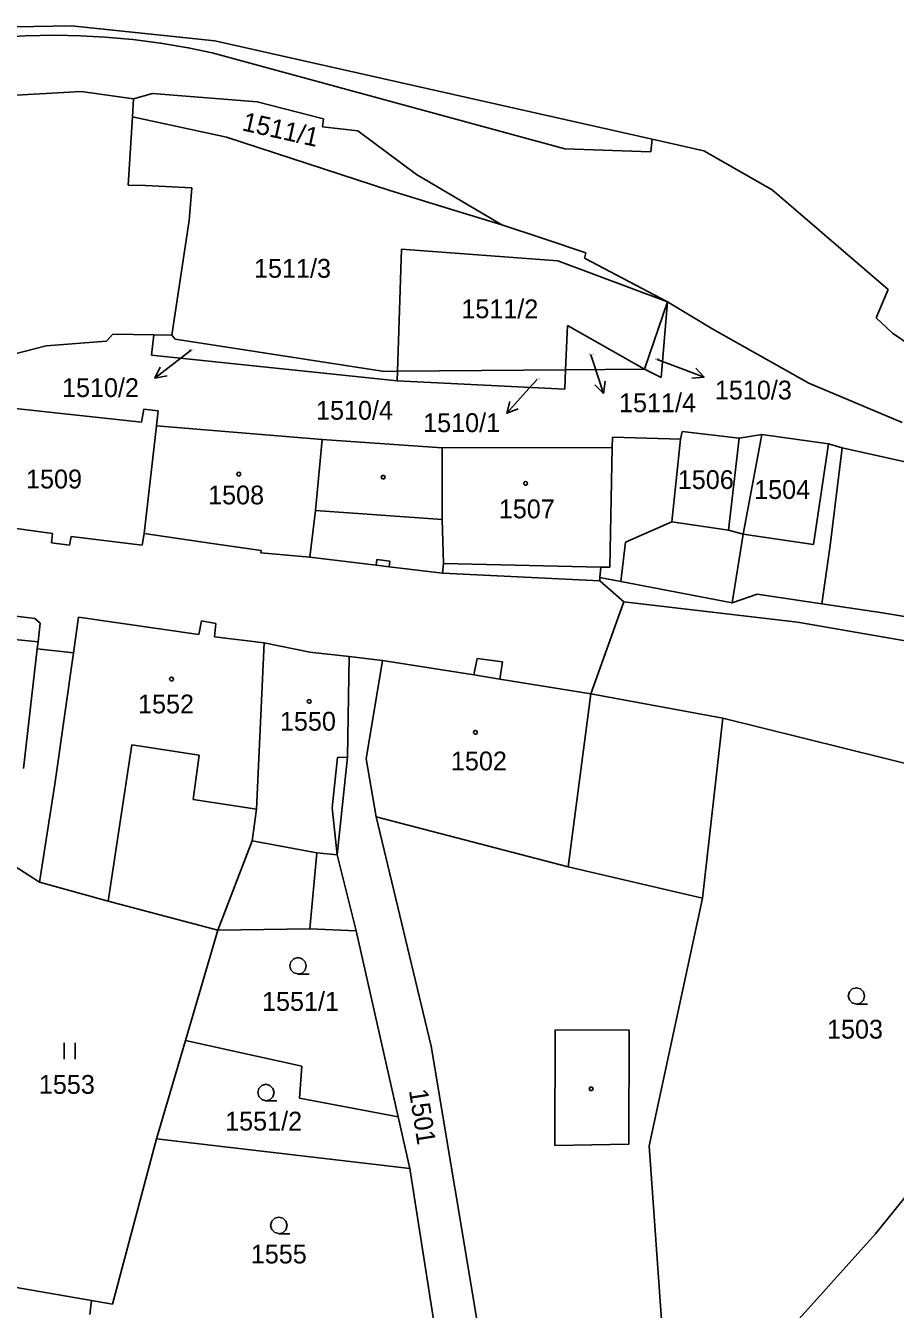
# Model space of a CAD drawing. Extents: x -806774 to -803680, y -1151731 to -1150053.
# Drawn here: x -805431.7 to -805353.1, y -1150600.2 to -1150484.2 of the extents above; entities that cross this region are included whole.
import ezdxf

# ---------------------------------------------------------------- set-up
doc = ezdxf.new("R2010")
doc.units = 0
for name, color, linetype in [('1', 7, 'Continuous'), ('12', 7, 'Continuous'), ('2', 7, 'Continuous'), ('3', 7, 'Continuous'), ('4', 7, 'Continuous'), ('5', 7, 'Continuous'), ('7', 7, 'Continuous')]:
    doc.layers.add(name, color=color, linetype=linetype)

msp = doc.modelspace()

# ---------------------------------------------------------------- linework, layer by layer
at = {"layer": '1'}
for p, q in [((-805427.5, -1150484.17), (-805439.48, -1150484.39)), ((-805414.55, -1150485.55), (-805427.5, -1150484.17)), ((-805375.04, -1150494.44), (-805414.55, -1150485.55)), ((-805432.51, -1150490.44), (-805426.65, -1150490.12)), ((-805426.65, -1150490.12), (-805421.91, -1150490.78)), ((-805422.01, -1150492.41), (-805421.91, -1150490.78)), ((-805421.91, -1150490.78), (-805420.2, -1150490.31)), ((-805420.2, -1150490.31), (-805410.73, -1150491.06)), ((-805404.73, -1150492.58), (-805410.73, -1150491.06)), ((-805422.39, -1150498.58), (-805422.01, -1150492.41)), ((-805422.01, -1150492.41), (-805413.51, -1150494.25)), ((-805404.82, -1150493.31), (-805404.73, -1150492.58)), ((-805404.82, -1150493.31), (-805401.64, -1150493.66)), ((-805413.51, -1150494.25), (-805398.84, -1150499.03)), ((-805401.64, -1150493.66), (-805396.34, -1150497.62)), ((-805375.04, -1150494.44), (-805370.38, -1150495.49)), ((-805370.38, -1150495.49), (-805364.2, -1150499)), ((-805396.34, -1150497.62), (-805388.64, -1150502.18)), ((-805420.82, -1150498.62), (-805422.39, -1150498.58)), ((-805416.65, -1150498.81), (-805420.82, -1150498.62)), ((-805416.65, -1150498.81), (-805416.85, -1150501.41)), ((-805398.84, -1150499.03), (-805393.26, -1150500.75)), ((-805364.2, -1150499), (-805353.71, -1150508)), ((-805416.85, -1150501.41), (-805416.88, -1150501.78)), ((-805393.26, -1150500.75), (-805388.64, -1150502.18)), ((-805418.45, -1150512.13), (-805416.94, -1150502.17)), ((-805416.94, -1150502.17), (-805416.88, -1150501.78)), ((-805388.64, -1150502.18), (-805384.97, -1150503.36)), ((-805384.97, -1150503.36), (-805381.05, -1150504.71)), ((-805398.06, -1150515.4), (-805397.71, -1150504.36)), ((-805397.71, -1150504.36), (-805383.58, -1150505.43)), ((-805381.05, -1150504.71), (-805381.17, -1150505.18)), ((-805383.58, -1150505.43), (-805373.66, -1150509.12)), ((-805381.17, -1150505.18), (-805373.66, -1150509.12)), ((-805354.57, -1150510.01), (-805353.71, -1150508)), ((-805375.73, -1150515.2), (-805373.66, -1150509.12)), ((-805373.66, -1150509.12), (-805374.24, -1150515.95)), ((-805373.66, -1150509.12), (-805369.56, -1150511.61)), ((-805354.57, -1150510.01), (-805354.81, -1150510.56)), ((-805354.81, -1150510.56), (-805353.32, -1150511.97)), ((-805424.36, -1150512.68), (-805423.78, -1150512.05)), ((-805420.06, -1150512.11), (-805423.78, -1150512.05)), ((-805382.71, -1150511.26), (-805382.88, -1150515.26)), ((-805375.73, -1150515.2), (-805382.71, -1150511.26)), ((-805369.56, -1150511.61), (-805360.88, -1150516.47)), ((-805353.32, -1150511.97), (-805351.72, -1150513.04)), ((-805434.17, -1150514.23), (-805429.79, -1150513.09)), ((-805429.79, -1150513.09), (-805424.36, -1150512.68)), ((-805420.27, -1150513.95), (-805420.06, -1150512.11)), ((-805418.45, -1150512.13), (-805420.06, -1150512.11)), ((-805418.16, -1150512.5), (-805418.45, -1150512.13)), ((-805418.16, -1150512.5), (-805399.22, -1150515.41)), ((-805398.09, -1150516.27), (-805420.27, -1150513.95)), ((-805399.22, -1150515.41), (-805398.06, -1150515.4)), ((-805398.09, -1150516.27), (-805398.06, -1150515.4)), ((-805398.06, -1150515.4), (-805382.88, -1150515.26)), ((-805382.88, -1150515.26), (-805382.95, -1150517.01)), ((-805382.88, -1150515.26), (-805375.73, -1150515.2)), ((-805374.24, -1150515.95), (-805375.73, -1150515.2)), ((-805382.95, -1150517.01), (-805398.09, -1150516.27)), ((-805360.88, -1150516.47), (-805352.47, -1150520.04)), ((-805421.2, -1150520), (-805435.67, -1150518.44)), ((-805420.99, -1150518.84), (-805421.2, -1150520)), ((-805419.68, -1150518.99), (-805420.99, -1150518.84)), ((-805419.83, -1150520.32), (-805419.68, -1150518.99)), ((-805420.95, -1150530.06), (-805419.83, -1150520.32)), ((-805404.85, -1150521.56), (-805419.83, -1150520.32)), ((-805372.5, -1150521.53), (-805372.33, -1150520.86)), ((-805372.33, -1150520.86), (-805367.19, -1150521.46)), ((-805367.19, -1150521.46), (-805365.15, -1150521.13)), ((-805365.15, -1150521.13), (-805359.11, -1150521.95)), ((-805394.01, -1150522.33), (-805404.85, -1150521.56)), ((-805394.01, -1150522.33), (-805378.66, -1150522.3)), ((-805394.01, -1150528.79), (-805394.01, -1150522.33)), ((-805378.66, -1150522.3), (-805378.64, -1150521.35)), ((-805378.64, -1150521.35), (-805372.5, -1150521.53)), ((-805372.5, -1150521.53), (-805373.26, -1150529.02)), ((-805368.15, -1150529.77), (-805367.19, -1150521.46)), ((-805359.11, -1150521.95), (-805357.89, -1150522.31)), ((-805357.89, -1150522.31), (-805358.96, -1150531.16)), ((-805357.89, -1150522.31), (-805328.53, -1150528.95)), ((-805437.39, -1150528.93), (-805429.24, -1150530.06)), ((-805393.89, -1150532.77), (-805394.01, -1150528.79)), ((-805373.26, -1150529.02), (-805368.15, -1150529.77)), ((-805429.24, -1150530.06), (-805429.33, -1150530.91)), ((-805427.53, -1150530.33), (-805427.7, -1150531.12)), ((-805427.53, -1150530.33), (-805421.13, -1150531.13)), ((-805421.13, -1150531.13), (-805420.95, -1150530.06)), ((-805414.8, -1150530.96), (-805420.95, -1150530.06)), ((-805366.81, -1150530.13), (-805368.15, -1150529.77)), ((-805367.83, -1150536.33), (-805366.81, -1150530.13)), ((-805427.7, -1150531.12), (-805429.33, -1150530.91)), ((-805414.8, -1150530.96), (-805410.39, -1150531.59)), ((-805410.42, -1150531.81), (-805410.39, -1150531.59)), ((-805358.96, -1150531.16), (-805359.71, -1150536.42)), ((-805405.99, -1150532.21), (-805410.42, -1150531.81)), ((-805399.97, -1150532.93), (-805405.99, -1150532.21)), ((-805398.82, -1150533.07), (-805399.97, -1150532.93)), ((-805393.98, -1150533.66), (-805393.89, -1150532.77)), ((-805393.98, -1150533.66), (-805398.82, -1150533.07)), ((-805379.78, -1150534.34), (-805393.98, -1150533.66)), ((-805379.78, -1150534.34), (-805379.76, -1150534.04)), ((-805379.76, -1150534.04), (-805377.89, -1150534.4)), ((-805377.62, -1150536.23), (-805379.78, -1150534.34)), ((-805377.89, -1150534.4), (-805367.83, -1150536.33)), ((-805377.98, -1150537.24), (-805377.62, -1150536.23)), ((-805377.62, -1150536.23), (-805361.9, -1150538.09)), ((-805365.57, -1150535.55), (-805367.83, -1150536.33)), ((-805359.71, -1150536.42), (-805365.57, -1150535.55)), ((-805354.23, -1150537.22), (-805359.71, -1150536.42)), ((-805438.22, -1150536.87), (-805430.82, -1150537.74)), ((-805380.18, -1150543.39), (-805377.98, -1150537.24)), ((-805334.31, -1150540.65), (-805354.23, -1150537.22)), ((-805430.82, -1150537.74), (-805430.33, -1150538.18)), ((-805430.33, -1150538.18), (-805430.52, -1150539.85)), ((-805426.87, -1150537.61), (-805427.33, -1150540.86)), ((-805416.02, -1150539.19), (-805426.87, -1150537.61)), ((-805415.77, -1150537.95), (-805416.02, -1150539.19)), ((-805414.46, -1150538.19), (-805415.77, -1150537.95)), ((-805414.59, -1150539.39), (-805414.46, -1150538.19)), ((-805361.9, -1150538.09), (-805334.75, -1150542.8)), ((-805430.52, -1150539.85), (-805430.6, -1150540.49)), ((-805410.1, -1150539.94), (-805414.59, -1150539.39)), ((-805430.6, -1150540.49), (-805431.86, -1150551.3)), ((-805427.33, -1150540.86), (-805430.6, -1150540.49)), ((-805410.1, -1150539.94), (-805410.81, -1150554.99)), ((-805405.98, -1150540.8), (-805410.1, -1150539.94)), ((-805405.98, -1150540.8), (-805402.42, -1150541.17)), ((-805402.58, -1150550.27), (-805402.42, -1150541.17)), ((-805402.42, -1150541.17), (-805399.42, -1150541.54)), ((-805400.9, -1150550.42), (-805399.42, -1150541.54)), ((-805399.42, -1150541.54), (-805391.15, -1150542.84)), ((-805391.15, -1150542.84), (-805390.87, -1150541.36)), ((-805390.87, -1150541.36), (-805388.57, -1150541.66)), ((-805388.57, -1150541.66), (-805388.82, -1150543.22)), ((-805388.82, -1150543.22), (-805380.6, -1150544.56)), ((-805380.18, -1150543.39), (-805380.6, -1150544.56)), ((-805380.6, -1150544.56), (-805368.66, -1150546.75)), ((-805370.51, -1150563.03), (-805368.66, -1150546.75)), ((-805368.66, -1150546.75), (-805328.74, -1150556.64)), ((-805403.52, -1150559.11), (-805402.58, -1150550.27)), ((-805399.98, -1150555.67), (-805400.9, -1150550.42)), ((-805411.2, -1150557.84), (-805410.81, -1150554.99)), ((-805399.98, -1150555.67), (-805395.01, -1150576.39)), ((-805411.2, -1150557.84), (-805414.3, -1150565.9)), ((-805433.55, -1150559.55), (-805430.41, -1150561.57)), ((-805401.79, -1150565.96), (-805403.52, -1150559.11)), ((-805430.41, -1150561.57), (-805424.21, -1150563.29)), ((-805375.32, -1150585.4), (-805370.51, -1150563.03)), ((-805424.21, -1150563.29), (-805414.3, -1150565.9)), ((-805331.2, -1150563.91), (-805354.86, -1150593.35)), ((-805417.22, -1150575.88), (-805414.3, -1150565.9)), ((-805414.3, -1150565.9), (-805405.97, -1150565.79)), ((-805405.97, -1150565.79), (-805401.79, -1150565.96)), ((-805401.79, -1150565.96), (-805398, -1150582.78)), ((-805419.83, -1150584.77), (-805417.22, -1150575.88)), ((-805417.22, -1150575.88), (-805406.71, -1150578.2)), ((-805395.01, -1150576.39), (-805390.72, -1150602.19)), ((-805406.71, -1150578.2), (-805406.9, -1150581.1)), ((-805406.9, -1150581.1), (-805398, -1150582.78)), ((-805398, -1150582.78), (-805396.94, -1150587.46)), ((-805423.81, -1150599.71), (-805419.83, -1150584.77)), ((-805396.94, -1150587.46), (-805419.83, -1150584.77)), ((-805373.83, -1150606.21), (-805375.32, -1150585.4)), ((-805396.94, -1150587.46), (-805394.39, -1150603.79)), ((-805354.86, -1150593.35), (-805364.74, -1150604.34)), ((-805437.68, -1150597.31), (-805425.71, -1150599.38)), ((-805425.86, -1150600.64), (-805425.71, -1150599.38)), ((-805425.71, -1150599.38), (-805423.81, -1150599.71))]:
    msp.add_line(p, q, dxfattribs=at)
at = {"layer": '12'}
for p, q in [((-805420.95, -1150530.06), (-805419.83, -1150520.32)), ((-805404.85, -1150521.56), (-805419.83, -1150520.32)), ((-805405.48, -1150527.97), (-805404.85, -1150521.56)), ((-805394.01, -1150522.33), (-805378.66, -1150522.3)), ((-805394.01, -1150528.79), (-805394.01, -1150522.33)), ((-805378.88, -1150533.1), (-805378.66, -1150522.3)), ((-805405.99, -1150532.21), (-805405.48, -1150527.97)), ((-805393.89, -1150532.77), (-805394.01, -1150528.79)), ((-805414.8, -1150530.96), (-805420.95, -1150530.06)), ((-805414.8, -1150530.96), (-805410.39, -1150531.59)), ((-805410.42, -1150531.81), (-805410.39, -1150531.59)), ((-805405.99, -1150532.21), (-805410.42, -1150531.81)), ((-805379.68, -1150533.1), (-805393.89, -1150532.77)), ((-805378.88, -1150533.1), (-805379.68, -1150533.1)), ((-805426.87, -1150537.61), (-805427.33, -1150540.86)), ((-805416.02, -1150539.19), (-805426.87, -1150537.61)), ((-805415.77, -1150537.95), (-805416.02, -1150539.19)), ((-805414.46, -1150538.19), (-805415.77, -1150537.95)), ((-805414.59, -1150539.39), (-805414.46, -1150538.19)), ((-805410.1, -1150539.94), (-805414.59, -1150539.39)), ((-805429.02, -1150552.71), (-805427.33, -1150540.86)), ((-805410.1, -1150539.94), (-805410.81, -1150554.99)), ((-805410.1, -1150539.94), (-805410.81, -1150554.99)), ((-805405.98, -1150540.8), (-805410.1, -1150539.94)), ((-805405.98, -1150540.8), (-805402.42, -1150541.17)), ((-805402.58, -1150550.27), (-805402.42, -1150541.17)), ((-805400.9, -1150550.42), (-805399.42, -1150541.54)), ((-805399.42, -1150541.54), (-805391.15, -1150542.84)), ((-805391.15, -1150542.84), (-805388.82, -1150543.22)), ((-805388.82, -1150543.22), (-805380.6, -1150544.56)), ((-805380.6, -1150544.56), (-805382.64, -1150560.2)), ((-805422.07, -1150549.17), (-805424.21, -1150563.29)), ((-805415.98, -1150550.09), (-805422.07, -1150549.17)), ((-805416.53, -1150554.11), (-805415.98, -1150550.09)), ((-805403.49, -1150550.3), (-805403.95, -1150554.84)), ((-805402.58, -1150550.27), (-805403.49, -1150550.3)), ((-805399.98, -1150555.67), (-805400.9, -1150550.42)), ((-805430.41, -1150561.57), (-805429.02, -1150552.71)), ((-805410.81, -1150554.99), (-805416.53, -1150554.11)), ((-805411.2, -1150557.84), (-805410.81, -1150554.99)), ((-805403.95, -1150554.84), (-805403.52, -1150559.11)), ((-805382.64, -1150560.2), (-805399.98, -1150555.67)), ((-805411.2, -1150557.84), (-805405.34, -1150558.91)), ((-805405.34, -1150558.91), (-805403.52, -1150559.11)), ((-805430.41, -1150561.57), (-805424.21, -1150563.29))]:
    msp.add_line(p, q, dxfattribs=at)
at = {"layer": '3'}
for p, q in [((-805428.17, -1150576.08), (-805428.17, -1150577.58)), ((-805427.17, -1150577.58), (-805427.17, -1150576.08))]:
    msp.add_line(p, q, dxfattribs=at)
for points in [[(-805407.03, -1150569.87), (-805407.41, -1150569.77), (-805407.68, -1150569.5), (-805407.78, -1150569.13), (-805407.68, -1150568.76), (-805407.41, -1150568.49), (-805407.04, -1150568.39), (-805406.67, -1150568.49), (-805406.4, -1150568.76), (-805406.3, -1150569.14), (-805406.4, -1150569.52), (-805406.67, -1150569.79), (-805407.05, -1150569.89), (-805406.05, -1150569.89)], [(-805356.58, -1150572.59), (-805356.96, -1150572.49), (-805357.23, -1150572.22), (-805357.33, -1150571.85), (-805357.23, -1150571.48), (-805356.96, -1150571.21), (-805356.59, -1150571.11), (-805356.22, -1150571.21), (-805355.95, -1150571.48), (-805355.85, -1150571.86), (-805355.95, -1150572.24), (-805356.22, -1150572.51), (-805356.6, -1150572.61), (-805355.6, -1150572.61)], [(-805409.94, -1150581.32), (-805410.32, -1150581.22), (-805410.59, -1150580.95), (-805410.69, -1150580.58), (-805410.59, -1150580.21), (-805410.32, -1150579.94), (-805409.95, -1150579.84), (-805409.58, -1150579.94), (-805409.31, -1150580.21), (-805409.21, -1150580.59), (-805409.31, -1150580.97), (-805409.58, -1150581.24), (-805409.96, -1150581.34), (-805408.96, -1150581.34)], [(-805408.77, -1150593.33), (-805409.15, -1150593.23), (-805409.42, -1150592.96), (-805409.52, -1150592.59), (-805409.42, -1150592.22), (-805409.15, -1150591.95), (-805408.78, -1150591.85), (-805408.41, -1150591.95), (-805408.14, -1150592.22), (-805408.04, -1150592.6), (-805408.14, -1150592.98), (-805408.41, -1150593.25), (-805408.79, -1150593.35), (-805407.79, -1150593.35)]]:
    msp.add_lwpolyline(points, dxfattribs=at)
at = {"layer": '4'}
for p, q in [((-805382.93, -1150495.3), (-805414.79, -1150486.62)), ((-805375.04, -1150494.44), (-805375.18, -1150495.56)), ((-805375.18, -1150495.56), (-805382.93, -1150495.3)), ((-805366.81, -1150530.13), (-805365.15, -1150521.13)), ((-805405.48, -1150527.97), (-805404.85, -1150521.56)), ((-805378.88, -1150533.1), (-805378.66, -1150522.3)), ((-805359.11, -1150521.95), (-805360.46, -1150531.05)), ((-805405.99, -1150532.21), (-805405.48, -1150527.97)), ((-805405.48, -1150527.97), (-805394.01, -1150528.79)), ((-805373.26, -1150529.02), (-805377.47, -1150530.85)), ((-805360.46, -1150531.05), (-805366.81, -1150530.13)), ((-805377.47, -1150530.85), (-805377.89, -1150534.4)), ((-805399.97, -1150532.93), (-805399.91, -1150532.42)), ((-805399.91, -1150532.42), (-805398.76, -1150532.55)), ((-805398.76, -1150532.55), (-805398.82, -1150533.07)), ((-805379.68, -1150533.1), (-805393.89, -1150532.77)), ((-805379.76, -1150534.04), (-805379.68, -1150533.1)), ((-805378.88, -1150533.1), (-805379.68, -1150533.1)), ((-805434.2, -1150539.49), (-805430.52, -1150539.85)), ((-805429.02, -1150552.71), (-805427.33, -1150540.86)), ((-805391.15, -1150542.84), (-805388.82, -1150543.22)), ((-805380.6, -1150544.56), (-805382.64, -1150560.2)), ((-805422.07, -1150549.17), (-805424.21, -1150563.29)), ((-805415.98, -1150550.09), (-805422.07, -1150549.17)), ((-805416.53, -1150554.11), (-805415.98, -1150550.09)), ((-805403.49, -1150550.3), (-805403.95, -1150554.84)), ((-805402.58, -1150550.27), (-805403.49, -1150550.3)), ((-805430.41, -1150561.57), (-805429.02, -1150552.71)), ((-805410.81, -1150554.99), (-805416.53, -1150554.11)), ((-805403.95, -1150554.84), (-805403.52, -1150559.11)), ((-805382.64, -1150560.2), (-805399.98, -1150555.67)), ((-805411.2, -1150557.84), (-805405.34, -1150558.91)), ((-805405.34, -1150558.91), (-805405.97, -1150565.79)), ((-805405.34, -1150558.91), (-805403.52, -1150559.11)), ((-805382.64, -1150560.2), (-805370.51, -1150563.03)), ((-805383.83, -1150585.38), (-805383.81, -1150574.93)), ((-805383.81, -1150574.93), (-805377.12, -1150574.94)), ((-805377.12, -1150574.94), (-805377.14, -1150585.25)), ((-805377.14, -1150585.25), (-805383.83, -1150585.38))]:
    msp.add_line(p, q, dxfattribs=at)
msp.add_lwpolyline([(-805414.79, -1150486.62), (-805416.97, -1150486.17), (-805419.46, -1150485.75), (-805421.96, -1150485.43), (-805424.48, -1150485.2), (-805426.7, -1150485.09), (-805429.01, -1150485.04), (-805431.71, -1150485.08), (-805434.4, -1150485.24), (-805437.09, -1150485.5), (-805439.76, -1150485.88), (-805442.41, -1150486.36), (-805445.05, -1150486.94), (-805447.65, -1150487.64), (-805450.23, -1150488.44), (-805452.41, -1150489.21)], dxfattribs=at)
at = {"layer": '5'}
for points in [[(-805412.4, -1150524.53), (-805412.3, -1150524.55), (-805412.25, -1150524.64), (-805412.23, -1150524.7), (-805412.25, -1150524.79), (-805412.33, -1150524.86), (-805412.4, -1150524.87), (-805412.49, -1150524.84), (-805412.55, -1150524.78), (-805412.57, -1150524.7), (-805412.55, -1150524.61), (-805412.47, -1150524.54)], [(-805399.26, -1150524.81), (-805399.17, -1150524.96), (-805399.26, -1150525.11), (-805399.44, -1150525.11), (-805399.53, -1150524.96), (-805399.44, -1150524.81)], [(-805386.48, -1150525.36), (-805386.38, -1150525.38), (-805386.33, -1150525.47), (-805386.31, -1150525.53), (-805386.33, -1150525.62), (-805386.41, -1150525.69), (-805386.48, -1150525.7), (-805386.57, -1150525.67), (-805386.63, -1150525.61), (-805386.65, -1150525.53), (-805386.63, -1150525.44), (-805386.55, -1150525.37)], [(-805418.48, -1150543.05), (-805418.38, -1150543.07), (-805418.33, -1150543.16), (-805418.31, -1150543.22), (-805418.33, -1150543.31), (-805418.41, -1150543.38), (-805418.48, -1150543.39), (-805418.57, -1150543.36), (-805418.63, -1150543.3), (-805418.65, -1150543.22), (-805418.63, -1150543.13), (-805418.55, -1150543.06)], [(-805406.04, -1150545.07), (-805405.94, -1150545.09), (-805405.89, -1150545.18), (-805405.87, -1150545.24), (-805405.89, -1150545.33), (-805405.97, -1150545.4), (-805406.04, -1150545.41), (-805406.13, -1150545.38), (-805406.19, -1150545.32), (-805406.21, -1150545.24), (-805406.19, -1150545.15), (-805406.11, -1150545.08)], [(-805391.02, -1150547.87), (-805390.92, -1150547.89), (-805390.87, -1150547.98), (-805390.85, -1150548.04), (-805390.87, -1150548.13), (-805390.95, -1150548.2), (-805391.02, -1150548.21), (-805391.11, -1150548.18), (-805391.17, -1150548.12), (-805391.19, -1150548.04), (-805391.17, -1150547.95), (-805391.09, -1150547.88)], [(-805380.48, -1150580.11), (-805380.39, -1150580.26), (-805380.48, -1150580.41), (-805380.66, -1150580.41), (-805380.75, -1150580.26), (-805380.66, -1150580.11)]]:
    msp.add_lwpolyline(points, close=True, dxfattribs=at)
at = {"layer": '7'}
for p, q in [((-805419.98, -1150516.03), (-805417.6, -1150514.2)), ((-805416.7, -1150513.5), (-805417.6, -1150514.2)), ((-805380.6, -1150513.92), (-805380.39, -1150514.56)), ((-805374.58, -1150514.34), (-805373.16, -1150514.87)), ((-805379.43, -1150517.4), (-805380.39, -1150514.56)), ((-805370.35, -1150515.93), (-805373.16, -1150514.87)), ((-805385.45, -1150516.14), (-805386.19, -1150516.97)), ((-805388.19, -1150519.2), (-805386.19, -1150516.97))]:
    msp.add_line(p, q, dxfattribs=at)
for points in [[(-805418.88, -1150515.82), (-805419.98, -1150516.03), (-805419.49, -1150515.03)], [(-805371.11, -1150515.11), (-805370.35, -1150515.93), (-805371.46, -1150516.04)], [(-805379.28, -1150516.3), (-805379.43, -1150517.4), (-805380.23, -1150516.62)], [(-805387.15, -1150518.79), (-805388.19, -1150519.2), (-805387.9, -1150518.12)]]:
    msp.add_lwpolyline(points, dxfattribs=at)

# ---------------------------------------------------------------- texts
at = {"layer": '2'}
for s, rotation, p in [('1511/1', 347.3843, (-805412.18, -1150493.62)), ('1501', 278.9732, (-805397.03, -1150580.39))]:
    msp.add_text(s, height=1.7, rotation=rotation, dxfattribs=at).set_placement(p)
for s, height, p in [('1511/3', 1.7, (-805411.02, -1150506.95)), ('1511/2', 1.7, (-805392.29, -1150510.61)), ('1510/2', 0.1, (-805416.91, -1150513.5)), ('1511/4', 0.1, (-805380.78, -1150513.92)), ('1510/3', 0.1, (-805374.79, -1150514.34)), ('1510/1', 0.1, (-805385.64, -1150516.14)), ('1510/4', 1.7, (-805405.42, -1150519.78)), ('1509', 1.7, (-805431.62, -1150525.99)), ('1506', 1.7, (-805372.73, -1150526.04)), ('1508', 1.7, (-805415.17, -1150527.43)), ('1504', 1.7, (-805365.83, -1150526.94)), ('1507', 1.7, (-805388.9, -1150528.69)), ('1552', 1.7, (-805421.5, -1150546.32)), ('1550', 1.7, (-805408.68, -1150547.88)), ('1502', 1.7, (-805393.23, -1150551.47)), ('1551/1', 1.7, (-805410.3, -1150573.2)), ('1503', 1.7, (-805359.25, -1150575.71)), ('1553', 1.7, (-805430.46, -1150580.7)), ('1551/2', 1.7, (-805413.63, -1150584.02)), ('1555', 1.7, (-805411.31, -1150596.03))]:
    msp.add_text(s, height=height, dxfattribs=at).set_placement(p)
at = {"layer": '7'}
for s, p in [('1510/2', (-805428.37, -1150517.73)), ('1510/3', (-805369.38, -1150517.95)), ('1511/4', (-805378.04, -1150519.1)), ('1510/1', (-805395.74, -1150520.9))]:
    msp.add_text(s, height=1.7, dxfattribs=at).set_placement(p)

doc.saveas('drawing.dxf')
